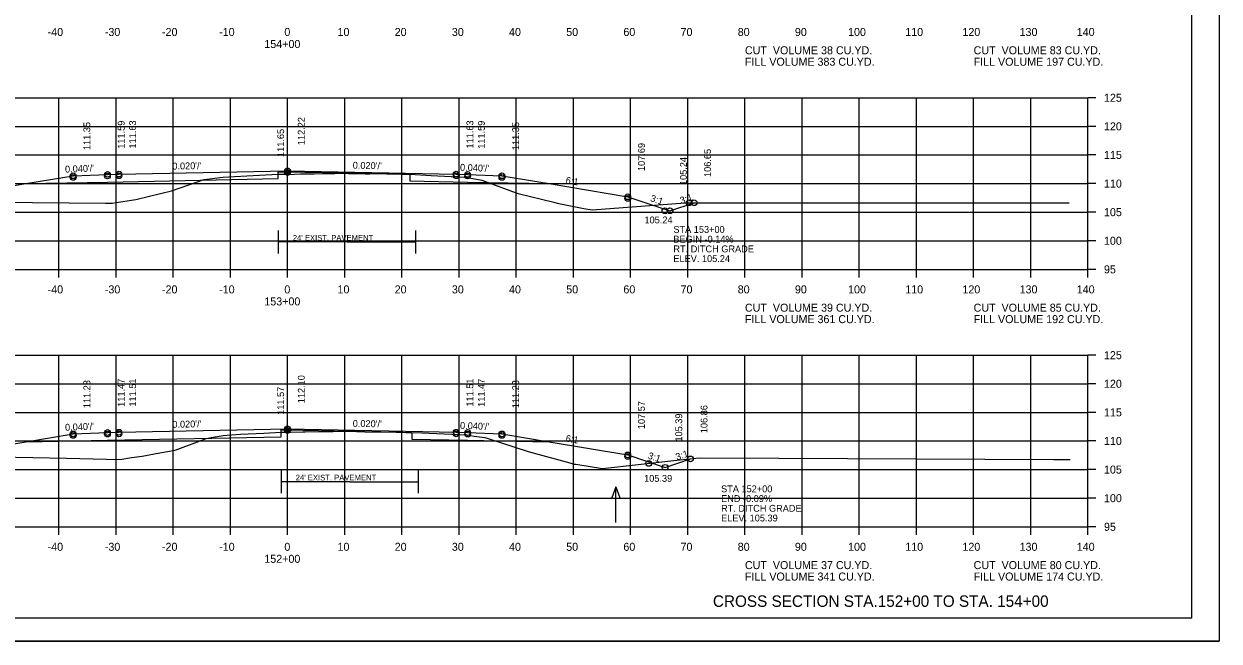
# Model space of a CAD drawing. Extents: x 1175611 to 1176402, y -433344 to -416213.
# Drawn here: x 1175734.9 to 1175943.9, y -429076.8 to -428968.9 of the extents above; entities that cross this region are included whole.
import ezdxf

# ---------------------------------------------------------------- set-up
doc = ezdxf.new("R2010")
doc.units = 0
for name, color, linetype in [('Default', 7, 'Continuous'), ('R_Alt Surface', 7, 'Continuous'), ('R_Axis', 7, 'Continuous'), ('R_Axis Annot', 7, 'Continuous'), ('R_Border', 7, 'Continuous'), ('R_Draft', 7, 'Continuous'), ('R_Exist Surface', 7, 'Continuous'), ('R_Fin Surface', 7, 'Continuous'), ('R_Grid', 7, 'Continuous'), ('R_No Plot', 7, 'Continuous'), ('R_Water Annot', 7, 'Continuous'), ('R_Xsect Elev', 7, 'Continuous'), ('R_Xsect Slope', 7, 'Continuous')]:
    doc.layers.add(name, color=color, linetype=linetype)

msp = doc.modelspace()

# ---------------------------------------------------------------- linework, layer by layer
at = {"layer": 'R_Alt Surface'}
for p, q in [((1175791.39, -429007), (1175779.39, -429007)), ((1175791.39, -429007), (1175803.39, -429007)), ((1175791.89, -429048.91), (1175779.89, -429048.91)), ((1175791.89, -429048.91), (1175803.89, -429048.91))]:
    msp.add_line(p, q, dxfattribs=at)
for points in [[(1175735.2, -428996.8), (1175749.47, -428996.52), (1175779.33, -428995.92), (1175779.33, -428994.75), (1175780.97, -428994.72), (1175802.33, -428995.15), (1175802.33, -428996.31), (1175812.47, -428996.52), (1175826.75, -428996.8)], [(1175779.39, -429009), (1175779.39, -429005)], [(1175803.39, -429009), (1175803.39, -429005)], [(1175735.2, -429041.93), (1175749.47, -429041.65), (1175779.85, -429041.04), (1175779.86, -429039.87), (1175780.97, -429039.85), (1175802.71, -429040.28), (1175802.71, -429041.45), (1175812.47, -429041.65), (1175826.75, -429041.93)], [(1175779.89, -429050.91), (1175779.89, -429046.91)], [(1175803.89, -429050.91), (1175803.89, -429046.91)]]:
    msp.add_lwpolyline(points, dxfattribs=at)
at = {"layer": 'R_Axis'}
for p, q in [((1175920.97, -429011.79), (1175920.97, -428981.79)), ((1175922.37, -428981.79), (1175920.97, -428981.79)), ((1175922.37, -428986.79), (1175920.97, -428986.79)), ((1175922.37, -428991.79), (1175920.97, -428991.79)), ((1175922.37, -428996.79), (1175920.97, -428996.79)), ((1175922.37, -429001.79), (1175920.97, -429001.79)), ((1175922.37, -429006.79), (1175920.97, -429006.79)), ((1175640.97, -429011.79), (1175920.97, -429011.79)), ((1175740.97, -429013.19), (1175740.97, -429011.79)), ((1175750.97, -429013.19), (1175750.97, -429011.79)), ((1175760.97, -429013.19), (1175760.97, -429011.79)), ((1175770.97, -429013.19), (1175770.97, -429011.79)), ((1175780.97, -429013.19), (1175780.97, -429011.79)), ((1175790.97, -429013.19), (1175790.97, -429011.79)), ((1175800.97, -429013.19), (1175800.97, -429011.79)), ((1175810.97, -429013.19), (1175810.97, -429011.79)), ((1175820.97, -429013.19), (1175820.97, -429011.79)), ((1175830.97, -429013.19), (1175830.97, -429011.79)), ((1175840.97, -429013.19), (1175840.97, -429011.79)), ((1175850.97, -429013.19), (1175850.97, -429011.79)), ((1175860.97, -429013.19), (1175860.97, -429011.79)), ((1175870.97, -429013.19), (1175870.97, -429011.79)), ((1175880.97, -429013.19), (1175880.97, -429011.79)), ((1175890.97, -429013.19), (1175890.97, -429011.79)), ((1175900.97, -429013.19), (1175900.97, -429011.79)), ((1175910.97, -429013.19), (1175910.97, -429011.79)), ((1175920.97, -429013.19), (1175920.97, -429011.79)), ((1175922.37, -429011.79), (1175920.97, -429011.79)), ((1175920.97, -429056.79), (1175920.97, -429026.79)), ((1175922.37, -429026.79), (1175920.97, -429026.79)), ((1175922.37, -429031.79), (1175920.97, -429031.79)), ((1175922.37, -429036.79), (1175920.97, -429036.79)), ((1175922.37, -429041.79), (1175920.97, -429041.79)), ((1175922.37, -429046.79), (1175920.97, -429046.79)), ((1175922.37, -429051.79), (1175920.97, -429051.79)), ((1175640.97, -429056.79), (1175920.97, -429056.79)), ((1175740.97, -429058.19), (1175740.97, -429056.79)), ((1175750.97, -429058.19), (1175750.97, -429056.79)), ((1175760.97, -429058.19), (1175760.97, -429056.79)), ((1175770.97, -429058.19), (1175770.97, -429056.79)), ((1175780.97, -429058.19), (1175780.97, -429056.79)), ((1175790.97, -429058.19), (1175790.97, -429056.79)), ((1175800.97, -429058.19), (1175800.97, -429056.79)), ((1175810.97, -429058.19), (1175810.97, -429056.79)), ((1175820.97, -429058.19), (1175820.97, -429056.79)), ((1175830.97, -429058.19), (1175830.97, -429056.79)), ((1175840.97, -429058.19), (1175840.97, -429056.79)), ((1175850.97, -429058.19), (1175850.97, -429056.79)), ((1175860.97, -429058.19), (1175860.97, -429056.79)), ((1175870.97, -429058.19), (1175870.97, -429056.79)), ((1175880.97, -429058.19), (1175880.97, -429056.79)), ((1175890.97, -429058.19), (1175890.97, -429056.79)), ((1175900.97, -429058.19), (1175900.97, -429056.79)), ((1175910.97, -429058.19), (1175910.97, -429056.79)), ((1175920.97, -429058.19), (1175920.97, -429056.79)), ((1175922.37, -429056.79), (1175920.97, -429056.79))]:
    msp.add_line(p, q, dxfattribs=at)
at = {"layer": 'R_Border'}
for q in [(1175939.15, -428867.33), (1175622.97, -429072.79)]:
    msp.add_line((1175939.15, -429072.79), q, dxfattribs=at)
at = {"layer": 'R_Exist Surface'}
for points in [[(1175729.96, -429000.04), (1175749.12, -429000.22), (1175750.38, -429000.23), (1175751.02, -429000.12), (1175754.41, -428999.56), (1175756.85, -428999.01), (1175760.7, -428998.08), (1175763.71, -428997.02), (1175766.37, -428996.08), (1175768.28, -428995.85), (1175769.12, -428995.75), (1175769.72, -428995.7), (1175771.69, -428995.58), (1175773.87, -428995.46), (1175779.33, -428995.17), (1175779.34, -428995.17), (1175779.42, -428995.16), (1175780.4, -428995.17), (1175781.32, -428995.18), (1175782.2, -428995.14), (1175783.22, -428995.09), (1175785.65, -428995.06), (1175788.12, -428995.03), (1175789.25, -428995.01), (1175790.52, -428994.99), (1175790.81, -428994.99), (1175790.87, -428994.99), (1175791.61, -428995.01), (1175792.42, -428995.02), (1175793.55, -428995.05), (1175794.52, -428995.07), (1175795.3, -428995.07), (1175796.12, -428995.05), (1175798.34, -428995.1), (1175800.83, -428995.16), (1175801.4, -428995.15), (1175802.03, -428995.14), (1175802.21, -428995.15), (1175802.33, -428995.16), (1175806.08, -428995.37), (1175811.9, -428995.69), (1175813.36, -428995.93), (1175814.93, -428996.2), (1175820.95, -428998.41), (1175821.3, -428998.54), (1175827.56, -429000.07), (1175828.15, -429000.22), (1175832.8, -429001.13), (1175834.26, -429001.41), (1175850.49, -429000.15), (1175850.64, -429000.14), (1175854.73, -429000.14), (1175914.71, -429000.16), (1175916.8, -429000.16), (1175917.68, -429000.16)], [(1175730.45, -429044.59), (1175742.31, -429044.8), (1175751.62, -429045), (1175753.65, -429044.69), (1175755.56, -429044.42), (1175758.62, -429043.88), (1175761.33, -429043.38), (1175765.2, -429041.93), (1175766.74, -429041.35), (1175767.62, -429041.2), (1175769.7, -429040.85), (1175770.38, -429040.75), (1175772.72, -429040.62), (1175776.85, -429040.4), (1175779.86, -429040.24), (1175781.12, -429040.26), (1175781.51, -429040.26), (1175783.64, -429040.2), (1175784.07, -429040.18), (1175788.17, -429040.12), (1175788.96, -429040.11), (1175789.29, -429040.1), (1175791.26, -429040.08), (1175791.42, -429040.09), (1175791.57, -429040.09), (1175792.72, -429040.1), (1175793.04, -429040.11), (1175793.18, -429040.12), (1175794.49, -429040.18), (1175794.85, -429040.18), (1175796.65, -429040.17), (1175797.24, -429040.18), (1175801.16, -429040.27), (1175801.64, -429040.28), (1175802.55, -429040.28), (1175802.71, -429040.29), (1175804.48, -429040.37), (1175808.39, -429040.55), (1175812.3, -429040.74), (1175813.63, -429040.93), (1175815.48, -429041.19), (1175816.05, -429041.38), (1175823.08, -429043.62), (1175830.33, -429045.62), (1175831.05, -429045.82), (1175831.38, -429045.87), (1175836.06, -429046.59), (1175848.52, -429045.23), (1175852.97, -429044.76), (1175866.91, -429044.82), (1175914.96, -429045.04), (1175915.4, -429045.04), (1175917.87, -429045.04)]]:
    msp.add_lwpolyline(points, dxfattribs=at)
at = {"layer": 'R_Fin Surface'}
for points in [[(1175718.76, -428999.99), (1175721.47, -428999.09), (1175735.2, -428996.8), (1175743.47, -428995.42), (1175749.47, -428995.18), (1175751.47, -428995.14), (1175780.97, -428994.55), (1175810.47, -428995.14), (1175812.47, -428995.18), (1175818.47, -428995.42), (1175826.75, -428996.8), (1175840.47, -428999.09), (1175847.86, -429001.55), (1175852.09, -429000.14)], [(1175720.42, -429044.57), (1175721.47, -429044.22), (1175735.2, -429041.93), (1175743.47, -429040.55), (1175749.47, -429040.31), (1175751.47, -429040.27), (1175780.97, -429039.68), (1175810.47, -429040.27), (1175812.47, -429040.31), (1175818.47, -429040.55), (1175826.75, -429041.93), (1175840.47, -429044.22), (1175847.01, -429046.4), (1175851.44, -429044.93)]]:
    msp.add_lwpolyline(points, dxfattribs=at)
at = {"layer": 'R_Grid'}
for p, q in [((1175640.97, -428981.79), (1175920.97, -428981.79)), ((1175740.97, -429011.79), (1175740.97, -428981.79)), ((1175750.97, -429011.79), (1175750.97, -428981.79)), ((1175760.97, -429011.79), (1175760.97, -428981.79)), ((1175770.97, -429011.79), (1175770.97, -428981.79)), ((1175780.97, -429011.79), (1175780.97, -428981.79)), ((1175790.97, -429011.79), (1175790.97, -428981.79)), ((1175800.97, -429011.79), (1175800.97, -428981.79)), ((1175810.97, -429011.79), (1175810.97, -428981.79)), ((1175820.97, -429011.79), (1175820.97, -428981.79)), ((1175830.97, -429011.79), (1175830.97, -428981.79)), ((1175840.97, -429011.79), (1175840.97, -428981.79)), ((1175850.97, -429011.79), (1175850.97, -428981.79)), ((1175860.97, -429011.79), (1175860.97, -428981.79)), ((1175870.97, -429011.79), (1175870.97, -428981.79)), ((1175880.97, -429011.79), (1175880.97, -428981.79)), ((1175890.97, -429011.79), (1175890.97, -428981.79)), ((1175900.97, -429011.79), (1175900.97, -428981.79)), ((1175910.97, -429011.79), (1175910.97, -428981.79)), ((1175920.97, -429011.79), (1175920.97, -428981.79)), ((1175640.97, -428986.79), (1175920.97, -428986.79)), ((1175640.97, -428991.79), (1175920.97, -428991.79)), ((1175640.97, -428996.79), (1175920.97, -428996.79)), ((1175640.97, -429001.79), (1175920.97, -429001.79)), ((1175640.97, -429006.79), (1175920.97, -429006.79)), ((1175640.97, -429011.79), (1175920.97, -429011.79)), ((1175640.97, -429026.79), (1175920.97, -429026.79)), ((1175740.97, -429056.79), (1175740.97, -429026.79)), ((1175750.97, -429056.79), (1175750.97, -429026.79)), ((1175760.97, -429056.79), (1175760.97, -429026.79)), ((1175770.97, -429056.79), (1175770.97, -429026.79)), ((1175780.97, -429056.79), (1175780.97, -429026.79)), ((1175790.97, -429056.79), (1175790.97, -429026.79)), ((1175800.97, -429056.79), (1175800.97, -429026.79)), ((1175810.97, -429056.79), (1175810.97, -429026.79)), ((1175820.97, -429056.79), (1175820.97, -429026.79)), ((1175830.97, -429056.79), (1175830.97, -429026.79)), ((1175840.97, -429056.79), (1175840.97, -429026.79)), ((1175850.97, -429056.79), (1175850.97, -429026.79)), ((1175860.97, -429056.79), (1175860.97, -429026.79)), ((1175870.97, -429056.79), (1175870.97, -429026.79)), ((1175880.97, -429056.79), (1175880.97, -429026.79)), ((1175890.97, -429056.79), (1175890.97, -429026.79)), ((1175900.97, -429056.79), (1175900.97, -429026.79)), ((1175910.97, -429056.79), (1175910.97, -429026.79)), ((1175920.97, -429056.79), (1175920.97, -429026.79)), ((1175640.97, -429031.79), (1175920.97, -429031.79)), ((1175640.97, -429036.79), (1175920.97, -429036.79)), ((1175640.97, -429041.79), (1175920.97, -429041.79)), ((1175640.97, -429046.79), (1175920.97, -429046.79)), ((1175640.97, -429051.79), (1175920.97, -429051.79)), ((1175640.97, -429056.79), (1175920.97, -429056.79))]:
    msp.add_line(p, q, dxfattribs=at)
at = {"layer": 'R_No Plot'}
msp.add_line((1175610.57, -429076.77), (1175943.91, -429076.77), dxfattribs=at)
msp.add_lwpolyline([(1175610.57, -428863.44), (1175943.91, -428863.44), (1175943.91, -429076.77), (1175610.57, -429076.77)], close=True, dxfattribs=at)
for centre in [(1175780.97, -428994.55), (1175780.97, -428994.84), (1175743.47, -428995.42), (1175743.47, -428995.71), (1175749.47, -428995.18), (1175749.47, -428995.47), (1175751.47, -428995.14), (1175751.47, -428995.43), (1175810.47, -428995.14), (1175810.47, -428995.43), (1175812.47, -428995.18), (1175812.47, -428995.47), (1175818.47, -428995.42), (1175818.47, -428995.71), (1175840.47, -428999.09), (1175840.47, -428999.38), (1175851.2, -429000.14), (1175852.09, -429000.14), (1175852.09, -429000.14), (1175846.98, -429001.55), (1175847.86, -429001.55), (1175847.86, -429001.55), (1175743.47, -429040.55), (1175743.47, -429040.82), (1175749.47, -429040.31), (1175749.47, -429040.58), (1175751.47, -429040.27), (1175751.47, -429040.54), (1175780.97, -429039.68), (1175780.97, -429039.95), (1175810.47, -429040.27), (1175810.47, -429040.54), (1175812.47, -429040.31), (1175812.47, -429040.58), (1175818.47, -429040.55), (1175818.47, -429040.82), (1175840.47, -429044.22), (1175840.47, -429044.49), (1175851.44, -429044.93), (1175851.44, -429044.93), (1175844.14, -429045.71), (1175844.14, -429045.71), (1175847.01, -429046.4), (1175847.01, -429046.4)]:
    msp.add_circle(centre, 0.5, dxfattribs=at)
at = {"layer": 'R_Water Annot'}
for p, q in [((1175838.41, -429049.78), (1175837.71, -429051.71)), ((1175838.41, -429056.07), (1175838.41, -429049.78)), ((1175838.41, -429049.78), (1175839.11, -429051.71))]:
    msp.add_line(p, q, dxfattribs=at)

# ---------------------------------------------------------------- texts
at = {"layer": 'Default'}
for s, p in [('CUT  VOLUME 38 CU.YD.', (1175860.97, -428974.19)), ('CUT  VOLUME 83 CU.YD.', (1175900.97, -428974.19)), ('FILL VOLUME 383 CU.YD.', (1175860.97, -428976.19)), ('FILL VOLUME 197 CU.YD.', (1175900.97, -428976.19)), ('CUT  VOLUME 39 CU.YD.', (1175860.97, -429019.19)), ('CUT  VOLUME 85 CU.YD.', (1175900.97, -429019.19)), ('FILL VOLUME 361 CU.YD.', (1175860.97, -429021.19)), ('FILL VOLUME 192 CU.YD.', (1175900.97, -429021.19)), ('CUT  VOLUME 37 CU.YD.', (1175860.97, -429064.19)), ('CUT  VOLUME 80 CU.YD.', (1175900.97, -429064.19)), ('FILL VOLUME 341 CU.YD.', (1175860.97, -429066.19)), ('FILL VOLUME 174 CU.YD.', (1175900.97, -429066.19))]:
    msp.add_text(s, height=1.4, dxfattribs=at).set_placement(p)
at = {"layer": 'R_Alt Surface'}
for p in [(1175781.89, -429006.78), (1175782.4, -429048.69)]:
    msp.add_text("24' EXIST. PAVEMENT", height=1, dxfattribs=at).set_placement(p)
at = {"layer": 'R_Axis Annot'}
for s, p in [('-40', (1175739.01, -428970.99)), ('-30', (1175749.01, -428970.99)), ('-20', (1175759.01, -428970.99)), ('-10', (1175769.01, -428970.99)), ('0', (1175780.41, -428970.99)), ('10', (1175789.71, -428970.99)), ('20', (1175799.71, -428970.99)), ('30', (1175809.71, -428970.99)), ('40', (1175819.71, -428970.99)), ('50', (1175829.71, -428970.99)), ('60', (1175839.71, -428970.99)), ('70', (1175849.71, -428970.99)), ('80', (1175859.71, -428970.99)), ('90', (1175869.71, -428970.99)), ('100', (1175879.01, -428970.99)), ('110', (1175889.01, -428970.99)), ('120', (1175899.01, -428970.99)), ('130', (1175909.01, -428970.99)), ('140', (1175919.01, -428970.99)), ('154+00', (1175776.91, -428973.09)), ('125', (1175923.77, -428982.49)), ('120', (1175923.77, -428987.49)), ('115', (1175923.77, -428992.49)), ('110', (1175923.77, -428997.49)), ('105', (1175923.77, -429002.49)), ('100', (1175923.77, -429007.49)), ('95', (1175923.77, -429012.49)), ('-40', (1175739.01, -429015.99)), ('-30', (1175749.01, -429015.99)), ('-20', (1175759.01, -429015.99)), ('-10', (1175769.01, -429015.99)), ('0', (1175780.41, -429015.99)), ('10', (1175789.71, -429015.99)), ('20', (1175799.71, -429015.99)), ('30', (1175809.71, -429015.99)), ('40', (1175819.71, -429015.99)), ('50', (1175829.71, -429015.99)), ('60', (1175839.71, -429015.99)), ('70', (1175849.71, -429015.99)), ('80', (1175859.71, -429015.99)), ('90', (1175869.71, -429015.99)), ('100', (1175879.01, -429015.99)), ('110', (1175889.01, -429015.99)), ('120', (1175899.01, -429015.99)), ('130', (1175909.01, -429015.99)), ('140', (1175919.01, -429015.99)), ('153+00', (1175776.91, -429018.09)), ('125', (1175923.77, -429027.49)), ('120', (1175923.77, -429032.49)), ('115', (1175923.77, -429037.49)), ('110', (1175923.77, -429042.49)), ('105', (1175923.77, -429047.49)), ('100', (1175923.77, -429052.49)), ('95', (1175923.77, -429057.49)), ('-40', (1175739.01, -429060.99)), ('-30', (1175749.01, -429060.99)), ('-20', (1175759.01, -429060.99)), ('-10', (1175769.01, -429060.99)), ('0', (1175780.41, -429060.99)), ('10', (1175789.71, -429060.99)), ('20', (1175799.71, -429060.99)), ('30', (1175809.71, -429060.99)), ('40', (1175819.71, -429060.99)), ('50', (1175829.71, -429060.99)), ('60', (1175839.71, -429060.99)), ('70', (1175849.71, -429060.99)), ('80', (1175859.71, -429060.99)), ('90', (1175869.71, -429060.99)), ('100', (1175879.01, -429060.99)), ('110', (1175889.01, -429060.99)), ('120', (1175899.01, -429060.99)), ('130', (1175909.01, -429060.99)), ('140', (1175919.01, -429060.99)), ('152+00', (1175776.91, -429063.09))]:
    msp.add_text(s, height=1.4, dxfattribs=at).set_placement(p)
at = {"layer": 'R_Draft'}
msp.add_text('CROSS SECTION STA.152+00 TO STA. 154+00', height=2, dxfattribs=at).set_placement((1175855.37, -429070.79))
at = {"layer": 'R_Water Annot'}
for s, p in [('STA 153+00', (1175848.46, -429005.41)), ('BEGIN -0.14%', (1175848.46, -429007.11)), ('RT. DITCH GRADE', (1175848.46, -429008.81)), ('ELEV. 105.24', (1175848.46, -429010.51)), ('STA 152+00', (1175856.8, -429050.76)), ('END -0.09%', (1175856.8, -429052.46)), ('RT. DITCH GRADE', (1175856.8, -429054.16)), ('ELEV. 105.39', (1175856.8, -429055.86))]:
    msp.add_text(s, height=1.2, dxfattribs=at).set_placement(p)
at = {"layer": 'R_Xsect Elev'}
for s, p in [('111.35', (1175746.47, -428990.94)), ('111.59', (1175752.47, -428990.7)), ('111.63', (1175754.47, -428990.66)), ('112.22', (1175783.97, -428990.07)), ('111.63', (1175813.47, -428990.66)), ('111.59', (1175815.47, -428990.7)), ('111.35', (1175821.47, -428990.94)), ('111.65', (1175780.37, -428992.14)), ('107.69', (1175843.47, -428994.6)), ('105.24', (1175850.81, -428997.05)), ('106.65', (1175855.04, -428995.64)), ('111.23', (1175746.47, -429036.06)), ('111.47', (1175752.47, -429035.82)), ('111.51', (1175754.47, -429035.78)), ('112.10', (1175783.97, -429035.19)), ('111.51', (1175813.47, -429035.78)), ('111.47', (1175815.47, -429035.82)), ('111.23', (1175821.47, -429036.06)), ('111.57', (1175780.37, -429037.22)), ('107.57', (1175843.47, -429039.72)), ('106.86', (1175854.42, -429040.43)), ('105.39', (1175850, -429041.9))]:
    msp.add_text(s, height=1.2, rotation=90, dxfattribs=at).set_placement(p)
for s, p in [('105.24', (1175843.4, -429003.75)), ('105.39', (1175843.34, -429048.93))]:
    msp.add_text(s, height=1.2, dxfattribs=at).set_placement(p)
at = {"layer": 'R_Xsect Slope'}
for s, rotation, p in [("0.040'/'", 2.2906, (1175742.07, -428994.88)), ("0.020'/'", 1.1458, (1175760.83, -428994.35)), ("0.020'/'", 358.8542, (1175792.36, -428994.18)), ("0.040'/'", 357.7094, (1175811.12, -428994.53)), ('6:1', 350.5377, (1175829.55, -428996.76)), ('3:1', 18.4349, (1175849.82, -429000.37)), ('3:1', 341.5651, (1175844.32, -428999.85)), ("0.020'/'", 1.1458, (1175760.83, -429039.49)), ("0.020'/'", 358.8542, (1175792.36, -429039.31)), ("0.040'/'", 2.2906, (1175742.07, -429040.01)), ("0.040'/'", 357.7094, (1175811.12, -429039.66)), ('6:1', 350.5377, (1175829.55, -429041.89)), ('3:1', 341.5651, (1175843.9, -429044.84)), ('3:1', 18.4349, (1175849.07, -429045.19))]:
    msp.add_text(s, height=1.2, rotation=rotation, dxfattribs=at).set_placement(p)

doc.saveas('drawing.dxf')
